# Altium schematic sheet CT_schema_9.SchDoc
size 278 x 170 mm
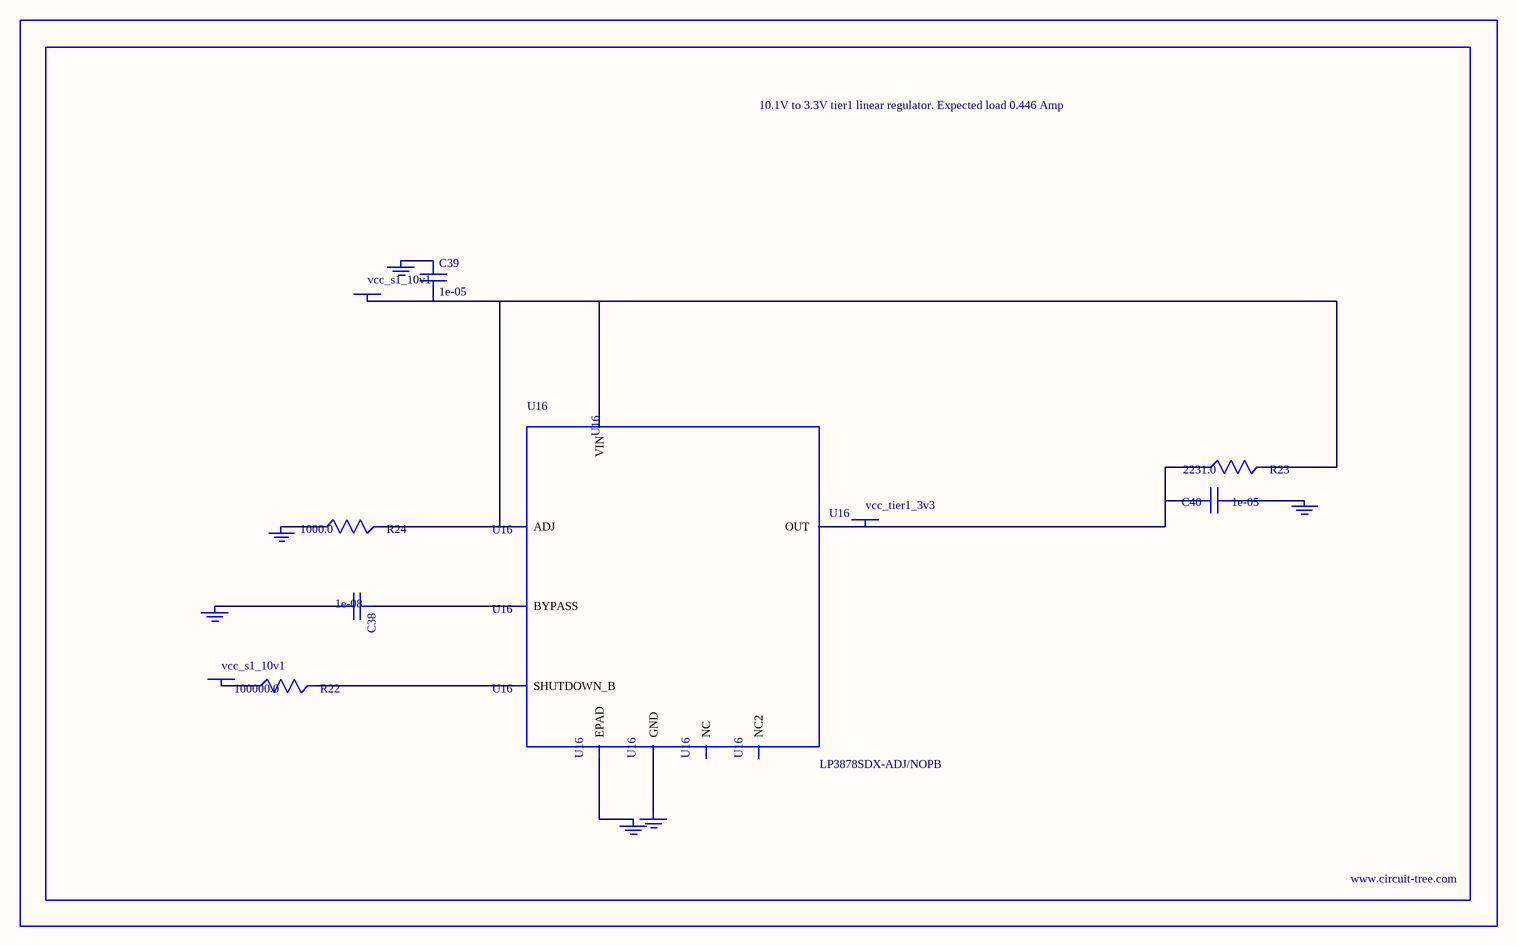
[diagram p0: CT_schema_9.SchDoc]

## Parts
BORDER8  (no value)
C38  1e-08  [C0402]
C39  1e-05  [C1206]
C40  1e-05  [C1210]
GND_INSTANCE_8_0  (no value)
GND_INSTANCE_8_1  (no value)
GND_INSTANCE_8_2  (no value)
GND_INSTANCE_8_3  (no value)
GND_INSTANCE_8_4  (no value)
GND_INSTANCE_8_5  (no value)
POWER_INSTANCE_8_0  vcc_s1_10v1
POWER_INSTANCE_8_1  vcc_s1_10v1
POWER_INSTANCE_8_2  vcc_tier1_3v3
R22  100000.0  [R0603]
R23  2231.0  [R0603]
R24  1000.0  [R0603]
U16  LP3878SDX-ADJ/NOPB  [WSON-8]

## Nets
NetC38_1: C38.1 U16.1(BYPASS)
NetC38_2: C38.2 GND_INSTANCE_8_0.0(GND)
NetC39_1: C39.1 GND_INSTANCE_8_1.0(GND)
NetC39_2: C39.2 POWER_INSTANCE_8_0.0(PWR) R23.2 R24.2 U16.4(VIN) U16.6(ADJ)
NetC40_1: C40.1 GND_INSTANCE_8_2.0(GND)
NetC40_2: C40.2 POWER_INSTANCE_8_2.0(PWR) R23.1 U16.5(OUT)
NetGND_INSTANCE_8_3_0: GND_INSTANCE_8_3.0(GND) R24.1
NetGND_INSTANCE_8_4_0: GND_INSTANCE_8_4.0(GND) U16.PAD(EPAD)
NetGND_INSTANCE_8_5_0: GND_INSTANCE_8_5.0(GND) U16.3(GND)
NetPOWER_INSTANCE_8_1_0: POWER_INSTANCE_8_1.0(PWR) R22.1
NetR22_2: R22.2 U16.8(SHUTDOWN_B)

Not connected (* = marked no-connect by the designer): U16 2(NC) 7(NC2)

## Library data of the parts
BORDER8 = BORDER_PAGE8
C38 = C0402C103K3RAC
C39 = C1206C106K3RACTU
C40 = GRM32DR61E106MA12L
GND_INSTANCE_8_0-GND_INSTANCE_8_5 = GND
POWER_INSTANCE_8_0-POWER_INSTANCE_8_2 = PWR
R22 = RC0603JR-07100KL
R23 = R23
R24 = RC0603JR-071KL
